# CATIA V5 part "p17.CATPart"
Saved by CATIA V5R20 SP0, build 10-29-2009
Part number: p17
Bounding box of the stored display mesh (mm): x -18 to -7, y 31.272 to 65.898, z 82.123 to 118.163
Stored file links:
  D:\Dropbox\IAO_2011\MMS_GR2\IAO_2011_1439_jlicbarski\p17.CATPart
  D:\Dropbox\IAO_2011\MMS_GR2\IAO_2011_1439_jlicbarski\train.CATProduct
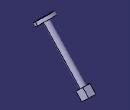
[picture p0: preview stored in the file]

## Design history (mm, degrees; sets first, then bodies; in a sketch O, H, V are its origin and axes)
AxisSystem1: origin (0, 0, 0), X (1, 0, 0), Y (0, 1, 0), Z (0, 0, 1)
Set1
  Line1: linked copy from another document
  Point1: linked copy from another document
  Line2: linked copy from another document
  Plane1: linked copy from another document
Body1 (main body)
  Plane2: type Normal, Curve Line1, RefPoint Point1
  Sketch1 on Plane2, origin (0, -13.7982, 14.6606), H (1, 0, 0), V (0, 0.7282, 0.6854)
    line L1 (-14.75, 107.0898) -> (-10.25, 107.0898)
    line L2 (-10.25, 107.0898) -> (-10.25, 101.0898)
    line L3 (-10.25, 101.0898) -> (-14.75, 101.0898)
    line L4 (-14.75, 101.0898) -> (-14.75, 107.0898)
    reference projected line E1 (-20, 104.0898) -> (0, 104.0898) from Line2
    reference intersected line E2 through (-12.5, 0) direction (0, 1) from Plane1
    distance L1 E1 = 3
    distance L1 L3 = 6
    distance L2 E2 = 2.25
    distance L2 L4 = 4.5
  Pad1: profile Sketch1, direction (0, -0.6854, 0.7282), length 3
  Sketch2 on start face of Pad1, origin (0, -13.7982, 14.6606), H (-1, 0, 0), V (0, 0.7282, 0.6854)
  Pad2: profile Sketch1, direction (0, 0.6854, -0.7282), length 2.5
  Sketch3 on end face of Pad1, origin (0, -15.8543, 16.8452), H (1, 0, 0), V (0, 0.7282, 0.6854)
    circle A1 centre (-12.5, 104.0898) radius 1.75
    reference projected point E1 (-12.5, 104.0898) from Line1
    radius A1 = 1.75
    distance A1 E1 = 1.75
  Pad3: profile Sketch3, direction (0, -0.6854, 0.7282), length 34
  Sketch4 on end face of Pad3, origin (0, -39.1567, 41.604), H (1, 0, 0), V (0, 0.7282, 0.6854)
    circle A1 centre (-12.5, 104.0898) radius 5.5
    reference projected point E1 (-12.5, 104.0898) from Line1
    radius A1 = 5.5
    distance A1 E1 = 5.5
  Pad4: profile Sketch4, direction (0, -0.6854, 0.7282), length 2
